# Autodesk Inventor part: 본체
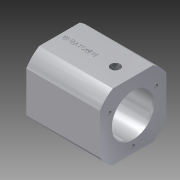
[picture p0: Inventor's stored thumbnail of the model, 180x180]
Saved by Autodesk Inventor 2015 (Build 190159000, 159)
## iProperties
Created: 2020-02
Part Number: 본체
Material: 알루미늄 6061
Document SubType Name: Modeling
Designer: LINEART-SSD.D4.16.05
Density: 2.7 g/cm^3
Appearance: 알루미늄 - 평지
Mass: 537.473 g
Surface Area: 341.964 cm^2
Volume: 199.064 cm^3
Author: LINEART-SSD.D4.16.05
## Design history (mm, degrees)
sketch "스케치1"
  geometry: L1 (0, 0)-(83, 0); L2 (0, 0)-(0, 14); L3 (0, 14)-(12, 14); L4 (12, 14)-(12, 32); L5 (12, 32)-(83, 32); L6 (83, 32)-(83, 0)
  constraints: 12 end point, 4 perpendicular, 1 horizontal, 1 vertical
  dimensions: "d0" = 83 distance of L1.start L1.end; "d1" = 28 diameter of L3 L1; "d2" = 64 diameter of L5 L1; "d3" = 12 distance from line of L3.end L2
revolve "회전1" sketch "스케치1" stored, may be unused: angle "d4" = 90 deg
sketch "스케치2"
  geometry: 1 further point
hole "구멍1" sketch "스케치2" at (0, 0) diameter "d5" = 8.917; stored, may be unused: countersink angle "d9" = 90 deg, drill point angle "d11" = 118 deg; dims "d6" = 14, "d7" = 4, "d8" = 2, "d10" = 17
sketch "스케치3"
  geometry: L1 (0, 0)-(83, 0); L2 (83, 0)-(83, 20); L3 (83, 20)-(21, 20); L4 (21, 20)-(21, 0); L5 (19.679, 0)-(17, 4.458) reference; L6 (17, 4.458)-(0, 4.458) reference; L7 (0, 4.458)-(0, 14) reference; L8 (0, 14)-(12, 14) reference; L9 (12, 14)-(12, 32) reference; L10 (12, 32)-(83, 32) reference; L11 (83, 32)-(83, -32) reference; L12 (83, -32)-(12, -32) reference; L13 (12, -32)-(12, -14) reference; L14 (12, -14)-(0, -14) reference; L15 (0, -14)-(0, -4.458) reference; L16 (0, -4.458)-(17, -4.458) reference; L17 (17, -4.458)-(19.679, 0) reference
  constraints: 8 end point, 2 perpendicular, 1 collinear, 1 horizontal, 1 point on line, 1 vertical
  dimensions: "d12" = 40 diameter of L3 L1; "d13" = 62 distance between parallel lines of L4 L2
revolve "회전2" sketch "스케치3" stored, may be unused: angle "d14" = 90 deg
sketch "스케치4"
  geometry: C1 r 4.458 at (0, 0) reference; C2 r 14 at (0, 0) reference; C3 r 2 at (0, 0); 1 further point
  constraints: 1 centre point, 1 coincident
  dimensions: "d15" = 4 diameter of C3
extrude "돌출1" cut sketch "스케치4" distance "d16" = 45.5; taper "d17" = 0 deg
sketch "스케치5"
  geometry: L1 (-32, 32)-(32, 32); L2 (32, 32)-(32, -32); L3 (32, -32)-(-32, -32); L4 (-32, -32)-(-32, 32); L5 (-32, 32)-(32, -32); L6 (32, 32)-(-32, -32); C1 r 4.458 at (0, 0) reference; C2 r 14 at (0, 0) reference; C3 r 32 at (0, 0) reference; 1 further point
  constraints: 12 end point, 2 midpoint, 2 parallel, 1 horizontal, 1 perpendicular
  dimensions: "d18" = 64 distance of L2.end L3.end; "d19" = 64 distance of L1.end L2.end
extrude "돌출2" join sketch "스케치5" distance "d20" = 71; taper "d21" = 0 deg
sketch "스케치6"
  geometry: L1 (0, 0)-(0, 64) reference; L2 (0, 64)-(64, 64) reference; L3 (64, 64)-(64, 0) reference; L4 (64, 0)-(0, 0) reference; L5 (12.449, 64)-(51.551, 64); L6 (12.449, 0)-(51.551, 0); L7 (0, 51.551)-(0, 12.449); L8 (64, 51.551)-(64, 12.449); C1 r 4.458 at (32, 32) reference; C2 r 14 at (32, 32) reference; A1 r 37.5 centre (32, 32) between (12.449, 64) and (0, 51.551); A2 r 37.5 centre (32, 32) between (0, 12.449) and (12.449, 0); A3 r 37.5 centre (32, 32) between (51.551, 0) and (64, 12.449); A4 r 37.5 centre (32, 32) between (64, 51.551) and (51.551, 64); 1 further point
  constraints: 8 end point, 8 point on circle, 8 point on line, 4 centre point, 3 collinear, 3 concentric, 1 coincident
  dimensions: "d24" = 37.5 radius of A4
extrude "돌출3" cut sketch "스케치6" distance "d25" = 71; taper "d26" = 0 deg
sketch "스케치7" dims "d27" = 52
  geometry: L1 (51.551, -12.449)-(12.449, -12.449) reference; L2 (0, 0)-(0, 39.102) reference; L3 (12.449, 51.551)-(51.551, 51.551) reference; L4 (64, 39.102)-(64, 0) reference; C1 r 4.458 at (32, 19.551) reference; C2 r 14 at (32, 19.551) reference; A1 r 37.5 centre (32, 19.551) between (51.551, -12.449) and (64, 0) reference; A2 r 37.5 centre (32, 19.551) between (0, 0) and (12.449, -12.449) reference; A3 r 37.5 centre (32, 19.551) between (12.449, 51.551) and (0, 39.102) reference; A4 r 37.5 centre (32, 19.551) between (64, 39.102) and (51.551, 51.551) reference; 3 further points
  constraints: 2 vertical alignment, 1 coincident, 2 other
hole "구멍2" sketch "스케치7" at (32, 45.551) diameter "d28" = 3.242; stored, may be unused: countersink angle "d32" = 90 deg, drill point angle "d34" = 118 deg; dims "d29" = 10, "d30" = 4, "d31" = 2, "d33" = 12
sketch "스케치8" dims "d38" = 52
  geometry: L1 (0, 0)-(0, 39.102) reference; L2 (12.449, 51.551)-(51.551, 51.551) reference; L3 (64, 39.102)-(64, 0) reference; L4 (51.551, -12.449)-(12.449, -12.449) reference; C1 r 20 at (32, 19.551) reference; A1 r 37.5 centre (32, 19.551) between (0, 0) and (12.449, -12.449) reference; A2 r 37.5 centre (32, 19.551) between (12.449, 51.551) and (0, 39.102) reference; A3 r 37.5 centre (32, 19.551) between (64, 39.102) and (51.551, 51.551) reference; A4 r 37.5 centre (32, 19.551) between (51.551, -12.449) and (64, 0) reference; 3 further points
  constraints: 2 vertical alignment, 1 coincident, 2 other
hole "구멍3" sketch "스케치8" at (32, 45.551) diameter "d39" = 3.242; stored, may be unused: countersink angle "d43" = 90 deg, drill point angle "d45" = 118 deg; dims "d40" = 10, "d41" = 4, "d42" = 2, "d44" = 12
sketch "스케치9"
  geometry: L1 (71, 39.551)-(71, -0.449) reference; 2 further points
  constraints: 1 horizontal alignment
  dimensions: "d49" = 17 distance from line of point (54, 19.551) L1
hole "구멍4" sketch "스케치9" at (54, 19.551) diameter "d50" = 8.917; stored, may be unused: countersink angle "d54" = 90 deg, drill point angle "d56" = 118 deg; dims "d51" = 6, "d52" = 4, "d53" = 2, "d55" = 9
sketch "스케치10"
  geometry: L1 (0, 39.102)-(71, 39.102) reference; L2 (71, 39.102)-(71, 0) reference; L3 (71, 0)-(0, 0) reference; L4 (0, 0)-(0, 39.102) reference; C1 r 4.458 at (54, 19.551) reference; C2 r 2 at (54, 19.551); 1 further point
  constraints: 1 centre point, 1 coincident
  dimensions: "d57" = 4 diameter of C2
extrude "돌출4" cut sketch "스케치10" distance "d58" = 28.25; taper "d59" = 0 deg
sketch "스케치11"
  geometry: L1 (0, 5.551)-(0, 33.551) reference; 2 further points
  constraints: 1 horizontal alignment, 1 other
  dimensions: "d60" = 20 distance from line of point (20, 19.551) L1
feature "엠보싱1" sketch "스케치11" dims "d14" = 90 deg, "d61" = 0.5, "d62" = 0
chamfer "모따기2" distance "d66" = 1; stored, may be unused: second distance "d67" = 2, angle "d68" = 45 deg
chamfer "모따기3" distance "d69" = 1.8; stored, may be unused: second distance "d70" = 2, angle "d71" = 15 deg
node "솔리드1"
pattern_circular "원형 패턴1" dims angle "d36" = 360 deg
pattern_circular "원형 패턴2" dims angle "d47" = 360 deg
node "절단 모서리 투영1"
node "절단 모서리 투영2"
node "절단 모서리 투영3"
node "절단 모서리 투영4"
node "절단 모서리 투영5"
node "절단 모서리 투영6"
node "절단 모서리 투영7"
other parameters: "d22" = 75
